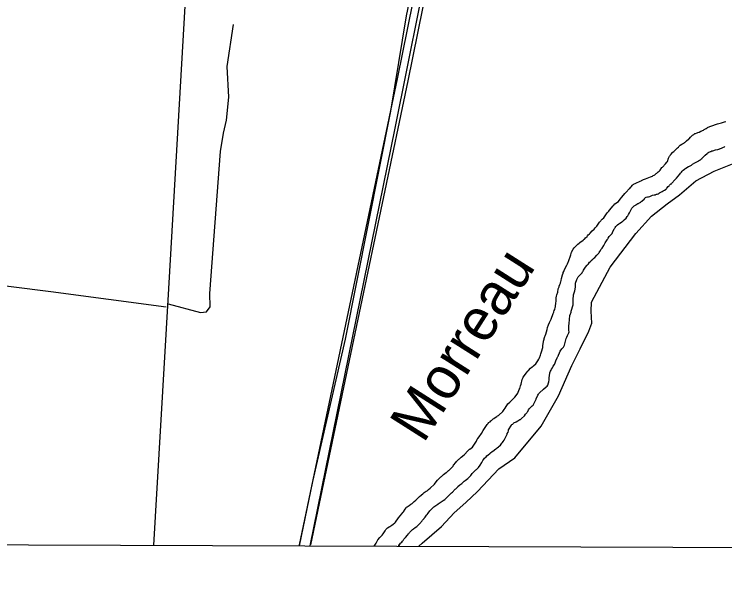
# Model space of a CAD drawing. Extents: x 3146026 to 3183936, y 897894 to 923344.
# Drawn here: x 3151989 to 3153937, y 907250 to 908790 of the extents above; entities that cross this region are included whole.
import ezdxf

# ---------------------------------------------------------------- set-up
doc = ezdxf.new("R2010")
doc.units = 0
for name, color, linetype in [('V-ANNO-SYMB', 7, 'Continuous'), ('V-RIVR-IDEN', 7, 'Continuous'), ('V-ROAD-CNTR', 7, 'Continuous'), ('V-TOPO-SHOR', 7, 'Continuous')]:
    doc.layers.add(name, color=color, linetype=linetype)

msp = doc.modelspace()

# ---------------------------------------------------------------- linework, layer by layer
at = {"layer": 'V-ANNO-SYMB'}
msp.add_lwpolyline([(3150260.2, 907341.2), (3165911.3, 907284.3), (3165898.4, 903734.3), (3150247.3, 903791.2)], close=True, dxfattribs=at)
at = {"layer": 'V-ROAD-CNTR'}
for points in [[(3153753.2, 912124.2), (3153647.3, 911628.4), (3153567.7, 911235.2), (3153533.4, 911067.8), (3153533.1, 911022), (3153526.2, 910970.1), (3153511.3, 910900.1), (3153469.5, 910650.4), (3153448.7, 910502.2), (3153416.7, 910449.9), (3153403.4, 910399.5), (3153384.7, 910306.6), (3153266.9, 909741.1), (3153038.3, 908612.9), (3152770.1, 907334.5)], [(3153782.5, 912117.9), (3153676.6, 911622.3), (3153597.1, 911229.2), (3153563.4, 911064.6), (3153563.1, 911020), (3153555.8, 910965), (3153540.8, 910894.5), (3153499.2, 910645.8), (3153477.5, 910491.9), (3153444.6, 910438), (3153432.6, 910392.7), (3153414.1, 910300.6), (3153296.3, 909735), (3153067.7, 908606.8), (3152800.8, 907334.4)]]:
    msp.add_lwpolyline(points, dxfattribs=at)
at = {"layer": 'V-TOPO-SHOR'}
for points in [[(3152770.7, 907332.1), (3152807.2, 907508.4), (3152896.9, 907898.5), (3153021.7, 908523.6), (3153064.7, 908784.9), (3153216.2, 909510.4), (3153318.7, 910020.5), (3153394.5, 910430.2)], [(3153447.4, 910428.8), (3153424.2, 910369.3), (3153416.1, 910338.2), (3153336.8, 909976.7), (3153232, 909469), (3153032.5, 908477.5), (3152799.4, 907332)], [(3152371.9, 907333.5), (3152411, 908005.2), (3152464, 908923.5), (3152492, 909344.1), (3152474.5, 909376.1)], [(3152410.7, 907995.5), (3152499.2, 907971.5), (3152516.1, 907973.5), (3152526.1, 907987.7), (3152524.6, 908023.8), (3152554.1, 908413.1), (3152562.7, 908463.4), (3152570.8, 908499.3), (3152577.3, 908561.8), (3152572.3, 908646.2), (3152589.8, 908761.3)], [(3153618.8, 908249.4), (3153621.2, 908252), (3153630.8, 908264.3), (3153632.5, 908266), (3153635.6, 908269.5), (3153645.4, 908276.5), (3153649.9, 908282.1), (3153655.2, 908288), (3153663, 908298.1), (3153667.4, 908302.2), (3153668, 908303), (3153669.3, 908304.1), (3153670, 908305.2), (3153671.5, 908306.9), (3153672.4, 908308.2), (3153674.1, 908309.7), (3153674.6, 908310.8), (3153675.5, 908311.4), (3153676.8, 908312.1), (3153678.3, 908314.2), (3153680.2, 908316.2), (3153683.7, 908320.5), (3153685.7, 908322.6), (3153687.7, 908323.7), (3153688.7, 908324.6), (3153691.8, 908325.9), (3153696.4, 908328.6), (3153701.1, 908330.3), (3153704.8, 908332.3), (3153707.4, 908333.1), (3153708.3, 908333.8), (3153714.6, 908336.1), (3153717, 908337.4), (3153719.4, 908338), (3153733.3, 908343.6), (3153738.7, 908345.9), (3153740.6, 908347.2), (3153743.3, 908348.5), (3153745.4, 908349.3), (3153749.3, 908352.8), (3153751.1, 908354.1), (3153754.8, 908357.5), (3153756.8, 908359), (3153759.6, 908362.3), (3153764.4, 908368.9), (3153765.9, 908370.7), (3153774.6, 908379.3), (3153778.3, 908383.8), (3153779.7, 908386.2), (3153782.5, 908394.8), (3153785.4, 908400.2), (3153786.2, 908401.1), (3153786.9, 908402.4), (3153788.7, 908404.1), (3153789.5, 908405.4), (3153794.8, 908411), (3153797.6, 908413.6), (3153800.4, 908415.7), (3153807.8, 908423), (3153809.8, 908425.2), (3153811.1, 908426.9), (3153814.4, 908430.4), (3153819.6, 908433.6), (3153822.6, 908435.1), (3153824.8, 908436.4), (3153826.3, 908437.6), (3153827.4, 908438.3), (3153832.4, 908442.6), (3153837.4, 908447.3), (3153839, 908448.4), (3153843.1, 908452.7), (3153846.6, 908455.9), (3153848.5, 908457.7), (3153851.8, 908460), (3153855.3, 908462.2), (3153857, 908463), (3153861.6, 908464.7), (3153863.3, 908465.1), (3153866.6, 908466.6), (3153871.8, 908468.6), (3153878.3, 908471.8), (3153879.4, 908472.6), (3153880.9, 908473.3), (3153882, 908474.1), (3153886.3, 908476.5), (3153888.7, 908478), (3153890, 908479.1), (3153891.8, 908479.9), (3153898.5, 908482.5), (3153901.3, 908483.7), (3153904.6, 908484.6), (3153912, 908486.9), (3153917, 908488.9), (3153928.5, 908492.2), (3153936.3, 908494.8), (3153939.7, 908495.6)], [(3153627.9, 908188.5), (3153630.5, 908193.7), (3153633.6, 908200.4), (3153634.7, 908201.9), (3153635.4, 908203.4), (3153636.2, 908204.5), (3153638, 908207.9), (3153642.6, 908212.2), (3153646.9, 908215.2), (3153649.1, 908216.5), (3153651, 908217.4), (3153655.2, 908220), (3153657.6, 908221.9), (3153660.4, 908224.5), (3153661.5, 908226), (3153666.3, 908230.7), (3153669.6, 908234.8), (3153671.1, 908237.2), (3153673.3, 908240.9), (3153675.5, 908245.2), (3153676.6, 908246.9), (3153677.5, 908249.1), (3153678.3, 908250.4), (3153682.5, 908257.7), (3153685.5, 908261.4), (3153688.8, 908264.1), (3153691.9, 908266.3), (3153692.9, 908266.7), (3153699, 908270.6), (3153700.1, 908270.8), (3153701.4, 908271.4), (3153707.1, 908274.6), (3153708.2, 908275.7), (3153709.7, 908276.6), (3153716.6, 908283.7), (3153717.3, 908284.5), (3153720.1, 908286.9), (3153721.9, 908288), (3153724.9, 908288.6), (3153726.2, 908288.6), (3153728.2, 908289), (3153731.2, 908290.1), (3153738.6, 908293.1), (3153743.6, 908294.3), (3153746.8, 908294.8), (3153748.3, 908295.2), (3153749.6, 908295.8), (3153751.6, 908296.2), (3153754.4, 908297.3), (3153757.5, 908298.8), (3153758.3, 908299.5), (3153765.1, 908303.1), (3153768.5, 908305.2), (3153772, 908307.2), (3153776.4, 908310.2), (3153777.2, 908311.5), (3153778.3, 908312.3), (3153782.3, 908317.1), (3153784.7, 908319.2), (3153785.5, 908320.5), (3153787.5, 908322.5), (3153789.5, 908324.2), (3153790.8, 908325), (3153792.1, 908326.3), (3153799.9, 908335.1), (3153802.1, 908337.1), (3153804.3, 908340.1), (3153813.7, 908351.3), (3153815.4, 908353.9), (3153818, 908356.9), (3153820.4, 908359.5), (3153823.3, 908362.1), (3153826.5, 908364.4), (3153827.6, 908365.5), (3153830.4, 908367.2), (3153837.2, 908372), (3153840.7, 908373.4), (3153846.1, 908376.2), (3153848.9, 908378.4), (3153854.6, 908382), (3153857.2, 908383.1), (3153863.9, 908386.7), (3153865.4, 908387.6), (3153867.4, 908389.1), (3153870.2, 908390.8), (3153873, 908393.2), (3153874.8, 908394.2), (3153875.4, 908395.3), (3153880, 908399.8), (3153882.4, 908401.8), (3153883.7, 908403.3), (3153888.7, 908407.6), (3153890.7, 908409.5), (3153893.7, 908411.2), (3153897.6, 908413.2), (3153898.7, 908413.4), (3153901.8, 908414.7), (3153904.6, 908415.3), (3153911.8, 908417.4), (3153918, 908418.9), (3153921.1, 908419.7)], [(3153921.1, 908419.7), (3153922.4, 908420.4), (3153923.9, 908420.8), (3153930.2, 908423.6), (3153933.7, 908425.5), (3153936.1, 908426.4), (3153937.4, 908427)], [(3153098.1, 907330.9), (3153107.3, 907339.2), (3153160.3, 907384.7), (3153195, 907422.4), (3153227, 907450.4), (3153259.1, 907480.9), (3153317.3, 907543.1), (3153361.4, 907573.3), (3153433.6, 907660.4), (3153481.5, 907743.5), (3153517.4, 907826.8), (3153540.2, 907871.9), (3153564.4, 907920.6), (3153572.2, 907942.1), (3153570.7, 907975.8), (3153571.3, 907999.9), (3153623.2, 908096), (3153693, 908188.1), (3153736.4, 908236.3), (3153779.4, 908270.1), (3153812.6, 908294.5), (3153858.1, 908333), (3153908.2, 908359.4), (3153967.8, 908383.1)], [(3153399, 907812.4), (3153404.7, 907818.7), (3153409.1, 907822.5), (3153411.5, 907824.3), (3153413.2, 907826), (3153419.3, 907831.1), (3153424.8, 907839.6), (3153427.2, 907843.9), (3153428, 907845.2), (3153429.1, 907847.5), (3153431.4, 907855.1), (3153432.7, 907858.8), (3153435.8, 907866.3), (3153437.7, 907873), (3153438.2, 907875.6), (3153438.4, 907880), (3153439.4, 907886.9), (3153439.4, 907888.4), (3153439.8, 907890.4), (3153439.8, 907892.5), (3153440.3, 907893.6), (3153441.6, 907898.4), (3153442, 907900.7), (3153444, 907905.9), (3153444.5, 907907.7), (3153446.2, 907912.4), (3153448, 907918.7), (3153449.6, 907925.2), (3153451.3, 907930.8), (3153454, 907937.5), (3153456.8, 907944.6), (3153459.5, 907950), (3153460.8, 907953.9), (3153462.1, 907956.5), (3153465.8, 907966.2), (3153466.9, 907968.6), (3153468, 907972.5), (3153468, 907973.6), (3153469.6, 907976.8), (3153470.7, 907979.6), (3153472.4, 907985.2), (3153472.9, 907987.4), (3153472.9, 907990.2), (3153473.1, 907992.6), (3153473.6, 907994.8), (3153475, 908005.4), (3153474.8, 908013.6), (3153475.2, 908015.3), (3153475.2, 908016.6), (3153476.8, 908020.5), (3153479, 908027.9), (3153480.6, 908036.3), (3153482.5, 908041.9), (3153483.2, 908044.3), (3153485.2, 908048.8), (3153486.3, 908052.1), (3153487, 908054.4), (3153487.2, 908056.2), (3153488.1, 908059.6), (3153489.6, 908065), (3153492.1, 908074.8), (3153493.6, 908079.7), (3153494.1, 908081.7), (3153495.4, 908084.3), (3153497.8, 908089.9), (3153503.9, 908101.6), (3153505.7, 908105.2), (3153507.4, 908110), (3153508.3, 908111.5), (3153514.5, 908130.3), (3153517.1, 908136.8), (3153521.7, 908145.4), (3153524.1, 908149.1), (3153525.7, 908151), (3153526.5, 908151.7), (3153533.9, 908158.8), (3153537.4, 908162), (3153540, 908163.5), (3153549.2, 908170.4), (3153551.1, 908172.5), (3153552.2, 908173.2), (3153555.1, 908176.4), (3153559.4, 908180.5), (3153560.7, 908182.2), (3153562.9, 908184.4), (3153565.1, 908186.9), (3153566.8, 908187.8), (3153566.8, 908188), (3153568.1, 908189.1), (3153573.6, 908195.3), (3153578.6, 908200.7), (3153581.4, 908203.5), (3153586, 908208.7), (3153591.9, 908217.1), (3153593.4, 908219), (3153596.9, 908222.9), (3153598.2, 908224.6), (3153601.3, 908227.4), (3153605, 908231.5), (3153614.8, 908244.7), (3153618.8, 908249.4)], [(3153451.6, 907772.2), (3153452.5, 907774.2), (3153452.7, 907775.7), (3153454.3, 907781.8), (3153455.8, 907786.9), (3153455.9, 907793.9), (3153456.1, 907798.4), (3153457.7, 907806), (3153459.5, 907811.2), (3153460.6, 907813.8), (3153461.9, 907816.1), (3153464.5, 907820.2), (3153466.7, 907824.3), (3153469.7, 907829.3), (3153471.7, 907833.6), (3153473.3, 907836.4), (3153473.9, 907838.8), (3153477.9, 907847.2), (3153479.4, 907850.9), (3153480.1, 907852), (3153481, 907854.6), (3153484, 907861.5), (3153486, 907865.4), (3153490.2, 907871.8), (3153495, 907877), (3153496, 907878.5), (3153497.4, 907882), (3153499.1, 907889.1), (3153502.5, 907900.6), (3153503.8, 907904.3), (3153505.8, 907908.8), (3153509.5, 907915.7), (3153510.2, 907918.7), (3153509.7, 907922.4), (3153509.8, 907928.5), (3153509.4, 907933.7), (3153509.4, 907935.2), (3153510.1, 907941.2), (3153510.3, 907941.5), (3153510.3, 907942.8), (3153511.7, 907951.9), (3153511.7, 907956.2), (3153511.9, 907960.3), (3153512.6, 907964), (3153513.5, 907965.7), (3153515.7, 907972.8), (3153516.1, 907975.4), (3153521.2, 907992.5), (3153521.2, 907994.9), (3153521.7, 907997.7), (3153521.3, 908005.9), (3153521.5, 908008.1), (3153521.8, 908018.1), (3153522.5, 908020), (3153524.7, 908028.7), (3153525.6, 908031.3), (3153526.7, 908036), (3153527.1, 908037.1), (3153527.6, 908041.2), (3153527.9, 908052), (3153531.6, 908061.8), (3153535.3, 908069.1), (3153542.3, 908077.1), (3153544.7, 908079.4), (3153545.8, 908080.7), (3153547.1, 908082.9), (3153549.1, 908085.5), (3153550, 908087.6), (3153555, 908095.8), (3153558.7, 908101), (3153559.6, 908101.6), (3153561.1, 908103.4), (3153563.1, 908105.1), (3153566.3, 908109.4), (3153568.5, 908111.6), (3153569.6, 908112.4), (3153570.9, 908113.9), (3153575.7, 908118.2), (3153577.5, 908120.2), (3153578.1, 908120.6), (3153580.3, 908122.7), (3153586, 908129.4), (3153588.8, 908131.8), (3153591.6, 908134.6), (3153592.9, 908136.3), (3153594.5, 908139.3), (3153598.2, 908145.4), (3153600.6, 908148.6), (3153605, 908155.3), (3153608.9, 908162.6), (3153610.9, 908165.4), (3153614.4, 908170.8), (3153614.8, 908171.9), (3153616.3, 908174.1), (3153617.4, 908176), (3153620.5, 908180.1), (3153622, 908181.8), (3153623.1, 908182.7), (3153625.3, 908185.3), (3153626.8, 908186.8), (3153627.9, 908188.5)], [(3152405.7, 907986), (3152089, 908028.1), (3151870.6, 908055.5), (3151645.1, 908085.5), (3151462.6, 908104.8), (3151436.2, 908107.9), (3151406.7, 908084.6), (3151287.2, 908027.5), (3151230.9, 907992.9), (3151186.3, 907945.9), (3151160.6, 907884), (3151144.7, 907826.6), (3151138.6, 907778.6), (3151140.8, 907677.4), (3151148.5, 907605), (3151149.4, 907549.6), (3151159.8, 907395.3)], [(3153042.6, 907408.3), (3153051.8, 907419.3), (3153054.2, 907423), (3153056, 907425.1), (3153061, 907432.7), (3153063.4, 907435.9), (3153064.5, 907437.6), (3153066.2, 907439.1), (3153071.9, 907442.8), (3153076.2, 907446), (3153079.9, 907448.2), (3153085.2, 907453.3), (3153089.9, 907457.4), (3153091.7, 907458.7), (3153095.6, 907462.6), (3153099.5, 907466.9), (3153104.1, 907470.5), (3153105.6, 907472), (3153108.9, 907474.4), (3153113, 907477.8), (3153118, 907481.5), (3153120.9, 907483.2), (3153125, 907486.2), (3153129.3, 907489.9), (3153140.7, 907500.8), (3153145.5, 907507.1), (3153149.6, 907511.8), (3153150.3, 907512.9), (3153153.6, 907516.8), (3153158.1, 907520.9), (3153159.9, 907522.2), (3153161.8, 907524.3), (3153163.6, 907525.8), (3153165.7, 907527.3), (3153169, 907530.1), (3153173.4, 907533.1), (3153174.9, 907533.8), (3153179.9, 907538.5), (3153180.3, 907538.7), (3153182.9, 907541.1), (3153192.1, 907550.6), (3153193.6, 907552.9), (3153200, 907560.5), (3153201.7, 907563.3), (3153207.4, 907569.3), (3153209.6, 907570.8), (3153214.6, 907574.7), (3153222.6, 907581.1), (3153233.1, 907593), (3153236.8, 907596.8), (3153237.9, 907597.3), (3153241.6, 907599.8), (3153245.3, 907602.9), (3153249.2, 907608), (3153250.5, 907610.4), (3153256, 907618.6), (3153258.4, 907624), (3153259.7, 907626.4), (3153263.2, 907630.5), (3153270.4, 907640), (3153274.6, 907648.2), (3153278.1, 907654), (3153285.3, 907664.8), (3153287.9, 907667.8), (3153289.6, 907669.7), (3153293.6, 907672.3), (3153295.7, 907674.4), (3153297.7, 907676), (3153298.4, 907676.8), (3153300.1, 907678.1), (3153302.3, 907680), (3153304.2, 907681.3), (3153307.5, 907683.9), (3153311.6, 907686.7), (3153314.2, 907688.2), (3153316.4, 907689), (3153317.9, 907690.1), (3153328.2, 907700.2), (3153332.5, 907705.8), (3153334.9, 907709.7), (3153337.4, 907714), (3153339.3, 907717.1), (3153342.6, 907720.9), (3153347.8, 907726.3), (3153353.5, 907731.7), (3153361.1, 907739.7), (3153364.6, 907743.8), (3153369.2, 907750.9), (3153373.4, 907761), (3153374.7, 907763.4), (3153376.9, 907770.3), (3153378.7, 907775.1), (3153380, 907779.6), (3153380.7, 907783.7), (3153381.6, 907787.6), (3153383.8, 907793.2), (3153384.6, 907794.8), (3153387.9, 907798.8), (3153392.9, 907805.7), (3153397.1, 907810.7), (3153399, 907812.4)], [(3153162.3, 907454.8), (3153164.7, 907456.1), (3153169.4, 907459.1), (3153170.7, 907460.2), (3153174, 907463.2), (3153179.5, 907469), (3153181, 907470.9), (3153182.1, 907471.6), (3153184.3, 907473.5), (3153185.6, 907475), (3153188, 907477.2), (3153190.1, 907479.5), (3153192.8, 907481.7), (3153194.3, 907483.4), (3153195.4, 907484.3), (3153198, 907487.1), (3153199.5, 907488.1), (3153204.3, 907492.9), (3153205.4, 907494.4), (3153210.6, 907499.3), (3153213, 907501.3), (3153215.8, 907503.2), (3153222.4, 907509), (3153225.4, 907511.1), (3153232.2, 907516.7), (3153235.4, 907519.5), (3153240.7, 907524.7), (3153244.8, 907530.3), (3153250.7, 907537), (3153254.8, 907540.6), (3153256.4, 907541.7), (3153259.2, 907544.3), (3153261.4, 907546.4), (3153263.8, 907549.5), (3153264.9, 907550.5), (3153266.4, 907552.7), (3153270.8, 907560.5), (3153273.6, 907566.3), (3153276.3, 907570), (3153278.6, 907572.5), (3153282.8, 907576.4), (3153284.5, 907578.4), (3153288.7, 907581.4), (3153292.8, 907585.2), (3153294.5, 907586.5), (3153299.6, 907590.8), (3153301.3, 907591.9), (3153308.9, 907597.5), (3153310.7, 907599), (3153313, 907600.5), (3153317, 907603.7), (3153318.7, 907605.2), (3153322, 907608.4), (3153326.1, 907613.2), (3153327.6, 907615.6), (3153329.8, 907618.4), (3153332.2, 907622), (3153335.1, 907627.4), (3153337.7, 907633), (3153338.2, 907634.3), (3153340.1, 907638), (3153340.8, 907639.7), (3153342.8, 907643.6), (3153343.9, 907647.7), (3153344.1, 907649.9), (3153345.6, 907652.9), (3153350.2, 907660.2), (3153352, 907662.6), (3153353.5, 907664.3), (3153355.5, 907665.8), (3153356.6, 907667.1), (3153358.9, 907668.9), (3153365, 907672.1), (3153369.8, 907675.1), (3153375.5, 907678.1), (3153376.6, 907678.5), (3153379.8, 907680.9), (3153387.7, 907688.8), (3153390.9, 907692.9), (3153393.3, 907695.5), (3153394.2, 907697), (3153395.5, 907698.7), (3153396.6, 907700.7), (3153399.2, 907704.6), (3153401, 907707.6), (3153404, 907711.2), (3153405.8, 907713), (3153409.1, 907715.8), (3153411.2, 907718.1), (3153414.7, 907723.3), (3153416.3, 907726.5), (3153419.6, 907734.3), (3153420.2, 907735.4), (3153424, 907744.7), (3153426.4, 907747.7), (3153427.5, 907749.4), (3153429.4, 907751.8), (3153439.7, 907761.9), (3153447.7, 907767.5), (3153450.1, 907770.1), (3153451.6, 907772.2)], [(3153042, 907331.1), (3153043.3, 907332.9), (3153048.3, 907338.8), (3153048.9, 907339.8), (3153051.1, 907342.2), (3153053.3, 907345), (3153054.4, 907345.9), (3153054.8, 907347), (3153057.2, 907349.8), (3153061.4, 907355.1), (3153066.6, 907361), (3153069.7, 907365.1), (3153071.4, 907366.8), (3153072.3, 907368.1), (3153073.6, 907369.6), (3153081.2, 907377.1), (3153083.8, 907379), (3153088.4, 907382), (3153092.5, 907385.3), (3153096.2, 907388.5), (3153099.1, 907391.5), (3153100.6, 907392.8), (3153103.4, 907396.2), (3153104.3, 907397.5), (3153105.6, 907398.8), (3153106.9, 907400.6), (3153108.4, 907402.1), (3153112.4, 907406.8), (3153113.2, 907407.7), (3153113.9, 907408.7), (3153115.9, 907410.9), (3153119.6, 907415.9), (3153121.1, 907418.2), (3153123.9, 907421.5), (3153128.5, 907427.5), (3153129.4, 907428.4), (3153131.6, 907431.2), (3153134.9, 907434.4), (3153136.2, 907435.9), (3153137.2, 907436.8), (3153139.2, 907438.7), (3153144.9, 907442.8), (3153149.9, 907446), (3153151.2, 907447.1), (3153156.4, 907450.5), (3153159.7, 907452.9), (3153161, 907453.5), (3153162.3, 907454.8)], [(3152975.9, 907331.3), (3152979, 907336.6), (3152980.9, 907339.2), (3152984.2, 907344.4), (3152986, 907348.7), (3152991.2, 907354.7), (3152994.9, 907358.2), (3152998, 907361.4), (3153000.1, 907364.8), (3153005.8, 907372.8), (3153008, 907376.3), (3153010.6, 907379.9), (3153012.4, 907381.4), (3153016.7, 907384.2), (3153018.9, 907385.1), (3153021.3, 907386.4), (3153024.3, 907388.3), (3153027.8, 907390.9), (3153032.4, 907395), (3153034.1, 907396.9), (3153042.6, 907408.3)], [(3153042.9, 907331.1), (3153048.3, 907338.8)]]:
    msp.add_lwpolyline(points, dxfattribs=at)

# ---------------------------------------------------------------- texts
at = {"layer": 'V-RIVR-IDEN'}
msp.add_text('Morreau', height=116, rotation=57.5675, dxfattribs=at).set_placement((3153110.8, 907610.4))

doc.saveas('drawing.dxf')
